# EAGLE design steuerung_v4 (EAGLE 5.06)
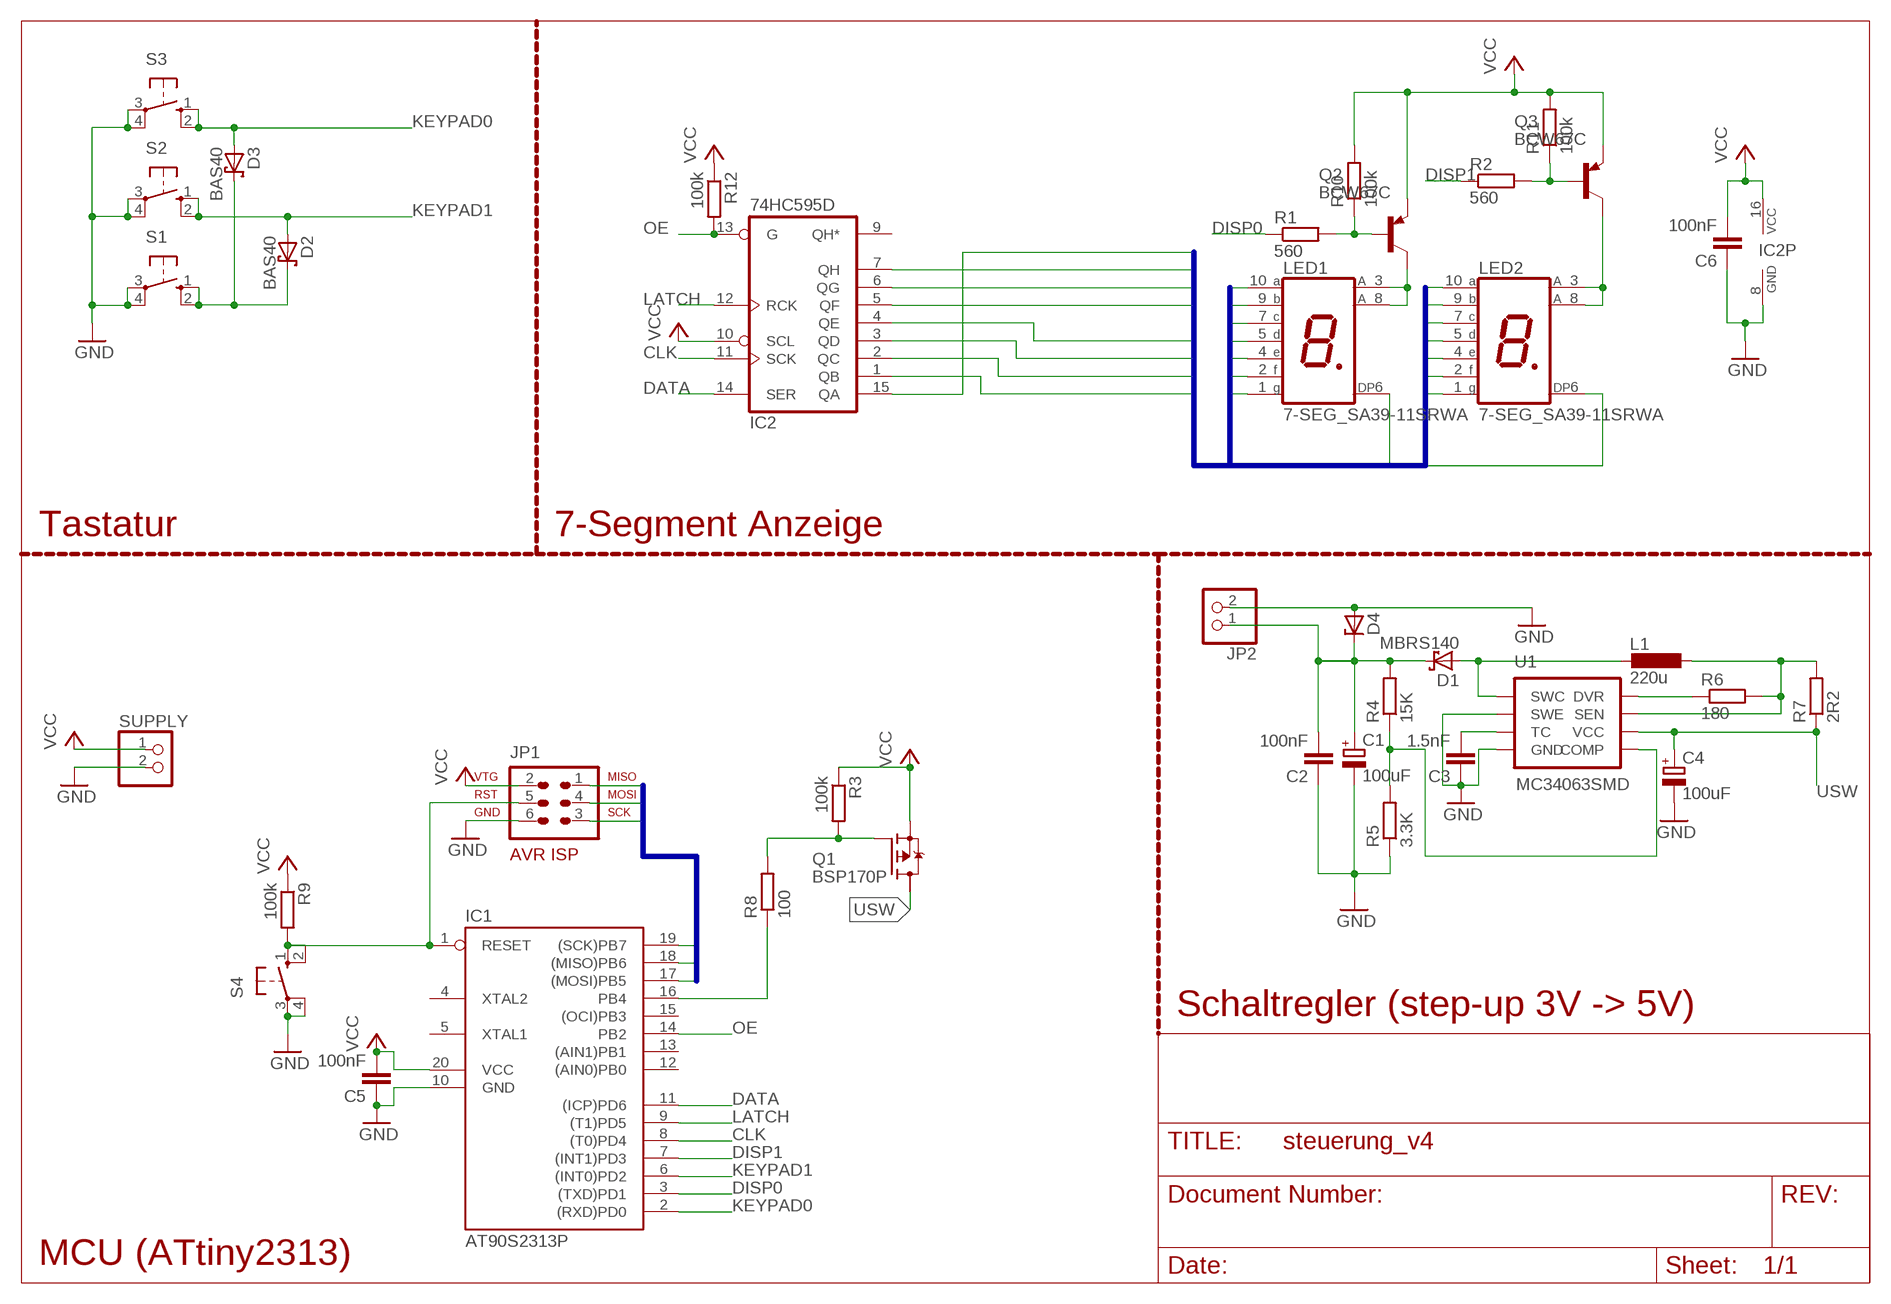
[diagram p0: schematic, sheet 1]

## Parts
C1  100uF  CPOL-EUD  [PANASONIC_D]
C2  100nF  C-EUC0805  [C0805]
C3  1.5nF  C-EUC0805  [C0805]
C4  100uF  CPOL-EUD  [PANASONIC_D]
C5  100nF  C-EUC0805K  [C0805K]
C6  100nF  C-EUC0805K  [C0805K]
D1  MBRS140  MBRS130LT3  [SMB]
D2  BAS40  [SOT23]
D3  BAS40  [SOT23]
D4  ZENER-DIODESOD80C  [SOD80C]
IC1  AT90S2313P  [DIL20]
IC2  74HC595D  [SO16]
JP1  AVR-ISP-6  [AVR-ISP-6]
JP2  PINHD-1X2  [1X02]
L1  220u  L-EUPIS2816  [PIS2816]
LED1  7-SEG_SA39-11SRWA  [SA39-11SRWA]
LED2  7-SEG_SA39-11SRWA  [SA39-11SRWA]
Q1  BSP170P  [SOT223]
Q2  BCW67C  BCW67  [SOT23]
Q3  BCW67C  BCW67  [SOT23]
R1  560  R-EU_R0805  [R0805]
R2  560  R-EU_R0805  [R0805]
R3  100k  R-EU_R0805  [R0805]
R4  15K  R-EU_R0805  [R0805]
R5  3.3K  R-EU_R0805  [R0805]
R6  180  R-EU_R0805  [R0805]
R7  2R2  R-EU_R0805  [R0805]
R8  100  R-EU_R0805  [R0805]
R9  100k  R-EU_R0805  [R0805]
R10  100k  R-EU_R0805  [R0805]
R11  100k  R-EU_R0805  [R0805]
R12  100k  R-EU_R0805  [R0805]
S1  10-XX  [B3F-10XX]
S2  10-XX  [B3F-10XX]
S3  10-XX  [B3F-10XX]
S4  10-XX  [B3F-10XX]
SUPPLY  PINHD-1X2  [1X02]
U1  MC34063SMD  [SO08]

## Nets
A: IC2.2(QC) LED1.10(A) LED2.10(A)
B: IC2.4(QE) LED1.9(B) LED2.9(B)
C: IC2.6(QG) LED1.7(C) LED2.7(C)
CLK: IC1.8((T0)PD4) IC2.11(SCK)
D: IC2.7(QH) LED1.5(D) LED2.5(D)
DATA: IC1.11((ICP)PD6) IC2.14(SER)
DISP0: IC1.3((TXD)PD1) R1.1
DISP1: IC1.7((INT1)PD3) R2.1
DP: IC2.15(QA) LED1.6(DP) LED2.6(DP)
E: IC2.5(QF) LED1.4(E) LED2.4(E)
F: IC2.3(QD) LED1.2(F) LED2.2(F)
G: IC2.1(QB) LED1.1(G) LED2.1(G)
GND: C1.- C2.1 C3.1 C4.- C5.1 C6.1 D4.A IC1.10(GND) IC2.8(GND) JP1.6 JP2.2 R5.1 S1.3(P) S1.4(P1) S2.3(P) S2.4(P1) S3.3(P) S3.4(P1) S4.3(P) S4.4(P1) SUPPLY.2 U1.2(SWE) U1.4(GND)
KEYPAD0: D3.1(A) IC1.2((RXD)PD0) S3.1(S) S3.2(S1)
KEYPAD1: D2.1(A) IC1.6((INT0)PD2) S2.1(S) S2.2(S1)
LATCH: IC1.9((T1)PD5) IC2.12(RCK)
MISO: IC1.18((MISO)PB6) JP1.1
MOSI: IC1.17((MOSI)PB5) JP1.4
N$1: LED1.3(A) LED1.8(A) Q2.3(C)
N$2: LED2.3(A) LED2.8(A) Q3.3(C)
N$3: Q3.1(B) R2.2 R11.1
N$4: Q2.1(B) R1.2 R10.1
N$7: IC1.16(PB4) R8.1
N$9: D1.A L1.2 U1.1(SWC)
N$10: C3.2 U1.3(TC)
N$11: R4.1 R5.2 U1.5(COMP)
N$12: C1.+ C2.2 D1.C D4.C JP2.1 R4.2
N$13: L1.1 R6.2 R7.2 U1.7(SEN)
N$14: R6.1 U1.8(DVR)
N$16: Q1.1(G) R3.2 R8.2
N$24: D2.3(C) D3.3(C) S1.1(S) S1.2(S1)
OE: IC1.14(PB2) IC2.13(G) R12.2
RST: IC1.1(RESET) JP1.5 R9.2 S4.1(S) S4.2(S1)
SCK: IC1.19((SCK)PB7) JP1.3
USW: C4.+ Q1.4(D1) R7.1 U1.6(VCC)
VCC: C5.2 C6.2 IC1.20(VCC) IC2.10(SCL) IC2.16(VCC) JP1.2 Q1.3(S) Q2.2(E) Q3.2(E) R3.1 R9.1 R10.2 R11.2 R12.1 SUPPLY.1
Unconnected: IC1.4(XTAL2) IC1.5(XTAL1) IC1.12((AIN0)PB0) IC1.13((AIN1)PB1) IC1.15((OCI)PB3) IC2.9(QH*) Q1.2(D)

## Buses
BUS1:A,B,C,D,E,F,G,DP
BUS2:MISO,MOSI,SCK

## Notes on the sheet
- Tastatur | 7-Segment Anzeige
- Schaltregler (step-up 3V -> 5V)
- MCU (ATtiny2313)

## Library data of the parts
C1 C4 = rcl:CPOL-EU: POLARIZED CAPACITOR, European symbol
C2 C3 C5 C6 = rcl:C-EU: CAPACITOR, European symbol
D1 = diode:MBRS130LT3: Schottky Power Rectifier
D2 D3 = diode:BAS40: Silicon Schottky Diodes
D4 = diode:ZENER-DIODE: Z-Diode
IC1 = atmel:AT90S2313: MICROCONTROLLER 2 Kbytes FLASH 128 bytes SRAM 128 bytes EEPROM UART
IC2 = 74xx-eu:74*595: 8-bit SHIFT REGISTER, output latch
JP1 = avr-5:AVR-ISP-6: AVR ISP-6 Serial Programming Header
JP2 SUPPLY = pinhead:PINHD-1X2: PIN HEADER
L1 = rcl:L-EU: INDUCTOR, European symbol
LED1 LED2 = display-kingbright:7-SEG_: Kingbright 14.2mm (0.56 INCH) SINGLE DIGIT NUMERIC DUISPLAY Source: SA56-11EWA(Ver1189471036.pdf
Q1 = transistor-fet:BSP170P: SIPMOS(R) Small-Signal-Transistor P-Channel, Enhancement mode Source: http://www.infineon.com/upload/Document/BSP170P_Rev2.4.pdf
Q2 Q3 = transistor-pnp:BCW67*
R1-R12 = rcl:R-EU_: RESISTOR, European symbol
S1-S4 = switch-omron:10-XX: OMRON SWITCH
U1 = SparkFun:MC34063

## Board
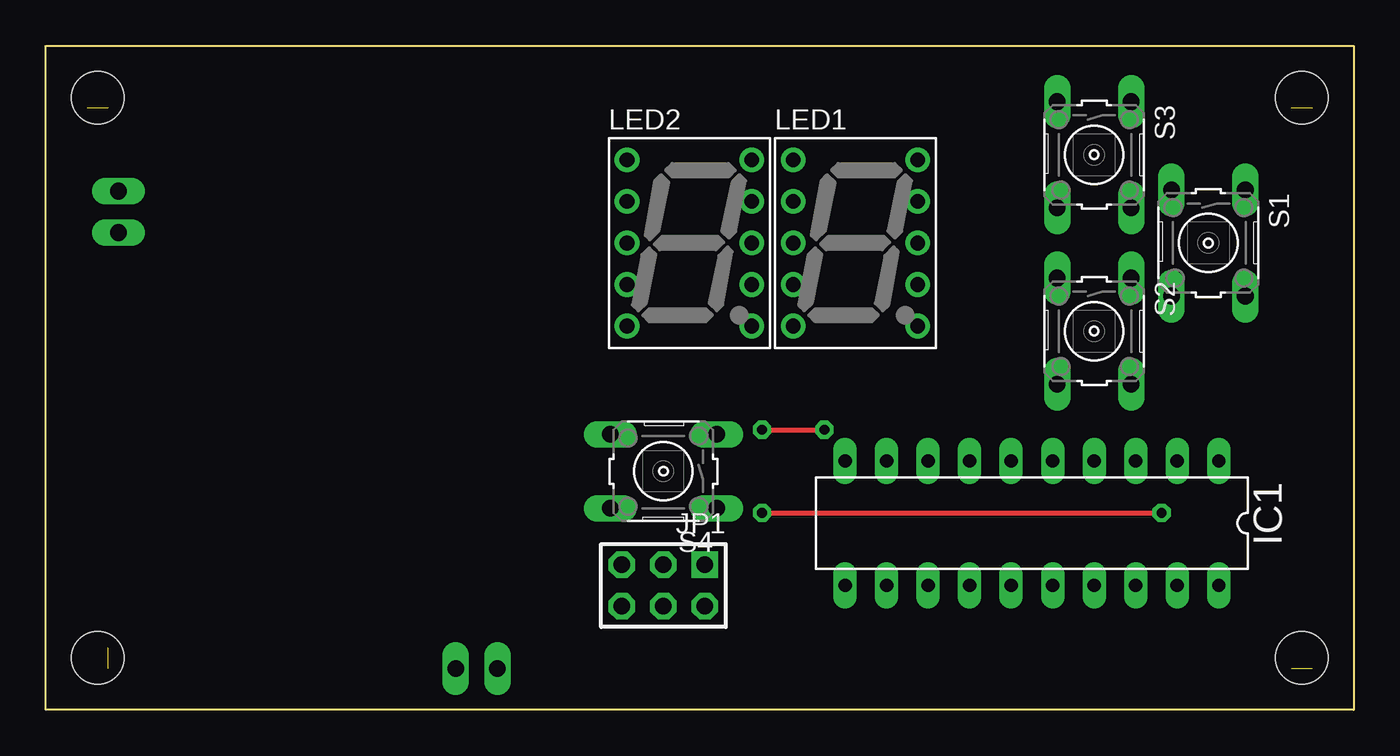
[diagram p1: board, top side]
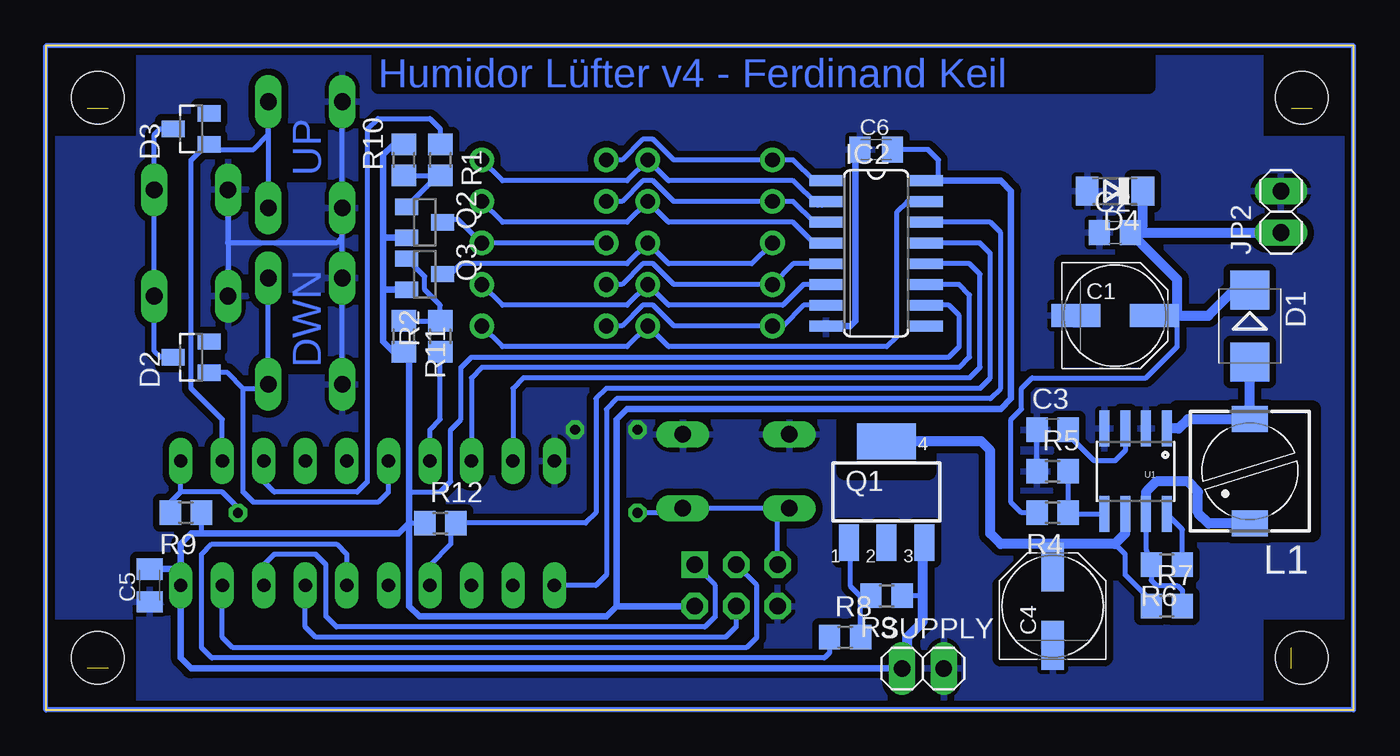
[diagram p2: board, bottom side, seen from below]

Size 80.01 x 40.64 mm. Coordinates in mm from the lower left corner, seen from the top.
Outline: 0,40.64 80.01,40.64 80.01,0 0,0 0,40.64
Copper layers (1*16): Top 0.035mm / dielectric 1.5mm / Bottom 0.035mm
Design rules "SparkFun": minimum track width 8mil, minimum drill 20mil, track to track 8mil, track to pad 8mil, pad to pad 8mil, via to via 8mil, smd to smd 8mil, copper to edge 10mil, drill to drill 8mil, minimum pad ring 12mil, minimum via ring 10mil, stop-mask expansion 4mil, vias tented up to drill 25mil, thermal gap 10mil
Holes 3.2 mm at 3.17,3.17 3.17,37.47 76.83,37.47 76.83,3.17
bRestrict: 30 lines

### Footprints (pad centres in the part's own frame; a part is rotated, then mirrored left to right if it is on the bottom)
PANASONIC_D = smd 3 x 1.4: + 2.4,0; - -2.4,0
C0805 = smd 1.3 x 1.5: 1 -0.95,0; 2 0.95,0
C0805K = smd 1.3 x 1.6: 1 -1,0; 2 1,0
SMB = smd 2.4 x 2.4: A 2.2,0; C -2.2,0
SOT23 = smd 1 x 1.4: 1 -0.95,-1.1; 2 0.95,-1.1; 3 0,1.1
SOD80C = smd 1.4 x 1.8: A 1.7,0; C -1.7,0
DIL20 = drill 0.813 long: 1 -11.43,-3.81; 2 -8.89,-3.81; 3 -6.35,-3.81; 4 -3.81,-3.81; 5 -1.27,-3.81; 6 1.27,-3.81; 7 3.81,-3.81; 8 6.35,-3.81; 9 8.89,-3.81; 10 11.43,-3.81; 11 11.43,3.81; 12 8.89,3.81; 13 6.35,3.81; 14 3.81,3.81; 15 1.27,3.81; 16 -1.27,3.81; 17 -3.81,3.81; 18 -6.35,3.81; 19 -8.89,3.81; 20 -11.43,3.81
SO16 = smd 0.66 x 2.032: 1 -4.445,-3.073; 2 -3.175,-3.073; 3 -1.905,-3.073; 4 -0.635,-3.073; 5 0.635,-3.073; 6 1.905,-3.073; 7 3.175,-3.073; 8 4.445,-3.073; 9 4.445,3.073; 10 3.175,3.073; 11 1.905,3.073; 12 0.635,3.073; 13 -0.635,3.073; 14 -1.905,3.073; 15 -3.175,3.073; 16 -4.445,3.073
AVR-ISP-6 = drill 1.016 square: 1 -2.54,-1.27 | drill 1.016 octagon: 2 -2.54,1.27; 3 0,-1.27; 4 0,1.27; 5 2.54,-1.27; 6 2.54,1.27
1X02 = drill 1.016 long: 1 -1.27,0; 2 1.27,0
PIS2816 = smd 2.2 x 1.6: 1 0,3.2; 2 0,-3.2
SA39-11SRWA = drill 0.9 pad 1.5 round: 1 -3.81,5.08; 2 -3.81,2.54; 3 -3.81,0; 4 -3.81,-2.54; 5 -3.81,-5.08; 6 3.81,-5.08; 7 3.81,-2.54; 8 3.81,0; 9 3.81,2.54; 10 3.81,5.08
SOT223 = smd 1.219 x 2.235: 1 -2.311,-3.099; 2 0,-3.099; 3 2.311,-3.099 | smd 3.6 x 2.2: 4 0,3.099
R0805 = smd 1.3 x 1.5: 1 -0.95,0; 2 0.95,0
B3F-10XX = drill 1.016 long: 1 -3.251,2.261; 2 3.251,2.261; 3 -3.251,-2.261; 4 3.251,-2.261
SO08 = smd 0.61 x 2.21: 1 -1.905,-2.616; 2 -0.635,-2.616; 3 0.635,-2.616; 4 1.905,-2.616; 5 1.905,2.616; 6 0.635,2.616; 7 -0.635,2.616; 8 -1.905,2.616

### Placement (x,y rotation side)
C1  14.61,24.13 0 bottom
C2  14.61,29.21 0 bottom
C3  18.41,17.14 0 bottom
C4  18.41,6.35 90 bottom
C5  73.66,7.62 90 bottom
C6  29.21,34.29 0 bottom
D1  6.35,23.5 270 bottom
D2  71.12,21.59 90 bottom
D3  71.12,35.56 90 bottom
D4  14.61,31.75 180 bottom
IC1  60.33,11.43 180 top
IC2  29.21,27.94 270 bottom
JP1  37.78,7.62 180 top
JP2  4.45,30.48 90 bottom
L1  6.35,14.61 180 bottom
LED1  49.53,28.57 0 top
LED2  39.37,28.57 0 top
Q1  28.57,13.34 0 bottom
Q2  56.83,29.84 270 bottom
Q3  56.83,26.67 270 bottom
R1  55.88,33.66 270 bottom
R2  55.88,22.86 90 bottom
R3  28.57,6.99 180 bottom
R4  18.41,12.06 180 bottom
R5  18.41,14.61 0 bottom
R6  11.43,8.89 180 bottom
R7  11.43,6.35 0 bottom
R8  31.11,4.45 0 bottom
R9  71.44,12.06 180 bottom
R10  58.1,33.66 90 bottom
R11  58.1,22.86 270 bottom
R12  55.88,11.43 0 bottom
S1  71.12,28.57 270 top
S2  64.14,23.18 270 top
S3  64.14,33.97 270 top
S4  37.78,14.61 180 top
SUPPLY  26.35,2.54 0 bottom
U1  13.34,14.61 180 bottom

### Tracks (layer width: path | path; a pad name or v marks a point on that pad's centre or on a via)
A
  Bottom 0.305: LED1.10 52.07,32.38 44.45,32.38 LED2.10 41.91,32.38 34.29,32.38 32.78,30.88 32.52,30.88 IC2.2
B
  Bottom 0.305: LED1.9 52.07,29.84 44.45,29.84 LED2.9 41.91,29.84 34.29,29.84 33.02,28.57 IC2.4
C
  Bottom 0.305: LED1.7 52.07,24.77 44.45,24.77 LED2.7 41.91,24.77 34.92,24.77 33.97,25.72 | 33.97,25.72 33.89,25.8 | IC2.6 33.66,26.04 33.97,25.72
CLK
  Bottom 0.305: IC2.11 24.13,26.04 23.5,25.4 23.5,21.59 24.13,20.95 53.34,20.95 53.98,20.32 IC1.8
D
  Bottom 0.305: LED1.5 44.77,23.5 43.5,24.77 42.86,24.77 41.59,23.5 LED2.5 34.92,23.5 33.66,24.77 IC2.7
DATA
  Bottom 0.305: IC2.14 22.23,29.84 21.59,29.21 21.59,19.68 22.23,19.05 45.09,19.05 45.72,18.41 45.72,8.26 46.35,7.62 IC1.11
DISP0
  Bottom 0.305: R1.1 55.88,35.56 56.52,36.2 59.69,36.2 60.33,35.56 60.33,13.97 60.96,13.34 66.04,13.34 66.67,13.97 IC1.3
DISP1
  Bottom 0.305: R2.1 55.88,17.78 56.52,17.14 IC1.7
DP
  Bottom 0.305: LED1.6 52.07,22.23 44.45,22.23 LED2.6 41.91,22.23 28.57,22.23 27.94,22.86 27.94,30.48 27.3,31.11 IC2.15
E
  Bottom 0.305: LED1.4 44.77,26.04 43.5,27.3 42.86,27.3 41.59,26.04 LED2.4 34.29,27.3 IC2.5
F
  Bottom 0.305: LED1.2 44.77,31.11 43.5,32.38 42.86,32.38 41.59,31.11 LED2.2 34.29,31.11 33.02,29.84 IC2.3
G
  Bottom 0.305: LED1.1 44.77,33.66 43.5,34.92 42.86,34.92 41.59,33.66 LED2.1 34.29,33.66 33.02,32.38 IC2.1
GND  (via drill 0.6)
  Top 0.305: v43.81,17.14 v47.62,17.14
  Bottom 0.305: R5.1 C3.1 | 30.48,34.06 C6.1 | 61.91,28.89 61.91,30.68 S3.4 | 61.91,28.89 61.91,28.57 | S3.4 S2.3 S2.4 | S3.4 S3.3 | S1.4 S1.3 68.86,28.61 68.9,28.57 62.23,28.57 61.91,28.89
  Bottom 0.406: IC2.8 30.8,23.5 30.48,23.81 30.48,34.06
  pour Bottom (isolate 0.406): 5.71,40.01 5.71,34.92 0.64,34.92 0.64,5.71 5.71,5.71 5.71,0.64 74.3,0.64 74.3,5.71 79.38,5.71 79.38,34.92 74.3,34.92 74.3,40.01
KEYPAD0
  Bottom 0.305: S3.2 S3.1 66.4,35.2 67.31,34.29 69.7,34.29 D3.1 70.34,34.29 70.48,34.29 71.12,33.66 71.12,19.68 69.22,17.78 IC1.2
KEYPAD1
  Bottom 0.305: S2.2 S2.1 | S2.2 66.43,19.93 | 67.94,19.68 67.94,13.34 67.31,12.7 59.69,12.7 59.05,13.34 IC1.6 | 67.94,19.68 66.64,19.68 S2.2 | D2.1 68.9,20.64 67.94,19.68
LATCH
  Bottom 0.305: IC2.12 23.5,27.3 22.86,26.67 22.86,20.95 23.5,20.32 50.8,20.32 51.44,19.68 IC1.9
MISO
  Bottom 0.305: IC1.18 66.67,8.89 66.04,9.53 63.5,9.53 62.87,8.89 62.87,5.71 62.23,5.08 39.69,5.08 39.05,5.71 39.05,7.62 JP1.1
MOSI
  Bottom 0.305: IC1.17 64.14,5.08 63.5,4.45 38.42,4.45 37.78,5.08 JP1.4
N$1
  Bottom 0.305: LED1.3 LED1.8 54.78,30.02 55.56,30.02 Q2.3
N$2
  Bottom 0.305: LED2.3 36.83,27.3 41.91,27.3 LED2.8 44.45,27.3 54.61,27.3 55.24,26.67 Q3.3
N$3
  Bottom 0.305: Q3.1 56.83,26.52 56.83,25.72 55.88,24.77 R2.2 R11.1
N$4
  Bottom 0.305: Q2.1 56.01,32.72 R1.2 R10.1
N$6  (1 unrouted)
  Bottom 0.254: 2.54,36.83 3.81,38.1 | 3.81,36.83 2.54,38.1
N$7
  Bottom 0.305: IC1.16 61.59,9.53 62.23,10.16 69.85,10.16 70.48,9.53 70.48,3.81 69.85,3.17 32.38,3.17 32.05,3.5 R8.1
N$9
  Bottom 0.61: U1.1 10.72,17.22 10.16,17.78 6.38,17.78 L1.2 D1.A
N$10
  Bottom 0.305: C3.2 17.46,16.83 15.88,15.24 14.61,15.24 13.97,15.88 U1.3
N$11
  Bottom 0.305: U1.5 17.39,11.99 R4.1 R5.2
N$12
  Bottom 0.305: R4.2 20.32,12.06 20.95,12.7 20.95,17.78 20.32,18.41 20.32,19.68 19.68,20.32 12.7,20.32 10.79,22.23 10.79,24.13
  Bottom 0.61: 10.79,24.13 C1.+ | C2.2 13.97,29.21 | 10.79,24.13 8.89,24.13 6.99,26.04 6.69,26.04 D1.C | 10.79,24.13 10.79,26.35 C2.2 | 13.34,29.21 JP2.1 | D4.C 12.9,29.64 13.34,29.21 | C2.2 13.34,29.21
N$13
  Bottom 0.305: U1.7 12.7,9.85 R6.2 12.38,7.93 12.06,7.62 10.79,7.62 10.48,7.3 R7.2
  Bottom 0.61: L1.1 8.87,11.4 9.53,12.06 9.53,13.34 10.16,13.97 12.06,13.97 12.7,13.34 U1.7
N$14
  Bottom 0.305: R6.1 10.48,11.04 U1.8
N$15  (1 unrouted)
  Bottom 0.254: 3.81,3.81 2.54,2.54 | 3.81,2.54 2.54,3.81
N$16
  Bottom 0.305: Q1.1 30.79,10.13 30.79,7.57 30.18,6.96 | 30.18,6.96 R3.2 | R8.2 30.18,6.96
N$18  (1 unrouted)
  Bottom 0.254: 76.2,36.83 77.47,38.1 | 77.47,36.83 76.2,38.1
N$19  (1 unrouted)
  Bottom 0.254: 77.47,2.54 76.2,3.81 | 76.2,2.54 77.47,3.81
N$24
  Bottom 0.305: 72.59,21.59 D2.3 73.03,21.59 73.38,21.95 S1.2 S1.1 73.38,35.2 73.03,35.56 D3.3 72.59,35.56
N$26
  Bottom 0.305: 0,0 0,40.64 80.01,40.64 80.01,0 0,0
OE
  Bottom 0.305: IC2.13 22.86,28.57 22.23,27.94 22.23,20.32 22.86,19.68 45.72,19.68 46.35,19.05 46.35,12.06 46.99,11.43 R12.2 55.24,11.12 55.24,10.16 56.52,8.89 IC1.14
RST  (via drill 0.6)
  Top 0.305: v43.81,12.06 v68.26,12.06
  Bottom 0.305: 35.24,12.34 S4.1 41.31,12.06 v43.81,12.06 | 35.24,12.34 S4.2 | JP1.5 35.24,12.34 | v68.26,12.06 67.94,12.06 69.22,13.34 71.75,13.34 | 71.75,13.34 IC1.1 | 71.75,13.34 72.39,12.7 R9.2
SCK
  Bottom 0.305: IC1.19 69.22,4.45 68.58,3.81 37.15,3.81 36.51,4.45 36.51,7.62 JP1.3
USW
  Bottom 0.305: R7.1 12.38,6.67 13.97,8.26 13.97,9.53 14.61,10.16
  Bottom 0.61: 29.21,17.07 29.21,17.14 Q1.4 22.78,16.43 22.23,15.88 22.23,10.79 21.59,10.16 18.41,10.16 | 18.41,10.16 14.61,10.16 13.97,10.79 U1.6 | 18.41,10.16 C4.+
VCC
  Bottom 0.305: IC2.10 24.77,24.77 24.13,24.13 24.13,22.23 24.77,21.59 53.98,21.59 54.61,20.95 54.61,17.78 55.24,17.14 55.24,13.97 55.88,13.34 57.78,13.34 | Q1.3 26.26,9.93 | 27.94,6.99 R3.1 26.35,6.99 | C6.2 26.04,34.29 25.4,33.66 25.4,32.38 IC2.16 | R9.1 70.49,10.8 70.48,10.79 | 57.78,11.43 R12.1
  Bottom 0.406: 58.75,21.92 R11.2 | 58.75,21.92 59.37,22.54 59.37,25.72 | 59.37,25.72 Q3.2 59.37,25.72 | 59.37,25.72 59.37,28.89 | 59.37,28.89 Q2.2 59.37,28.89 | 59.37,28.89 59.37,33.97 58.74,34.61 58.12,34.61 R10.2 | 58.75,21.92 58.12,21.92 57.78,21.59 57.78,13.34 57.78,11.43 | 25.4,32.38 21.59,32.38 20.95,31.75 20.95,19.05 21.59,18.41 44.45,18.41 45.09,17.78 45.09,6.35 | 45.09,6.35 45.72,5.71 57.15,5.71 57.78,6.35 57.78,11.43 | 45.09,6.35 JP1.2 | SUPPLY.1 71.12,2.54 71.75,3.17 IC1.20 71.75,8.26 | 71.75,8.26 71.75,10.16 71.12,10.79 70.48,10.79 58.42,10.79 57.78,11.43 | C5.2 72.12,8.62 71.75,8.26
  Bottom 0.61: Q1.3 26.04,10.01 26.2,10.01 26.35,10.16 26.35,6.99 26.35,5.4 27.3,4.45 27.3,2.86 SUPPLY.1
(copper drawn outside any net)
  shapes: Bottom circle x4

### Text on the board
Bottom: Humidor Lüfter v4 - Ferdinand Keil | UP | DWN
